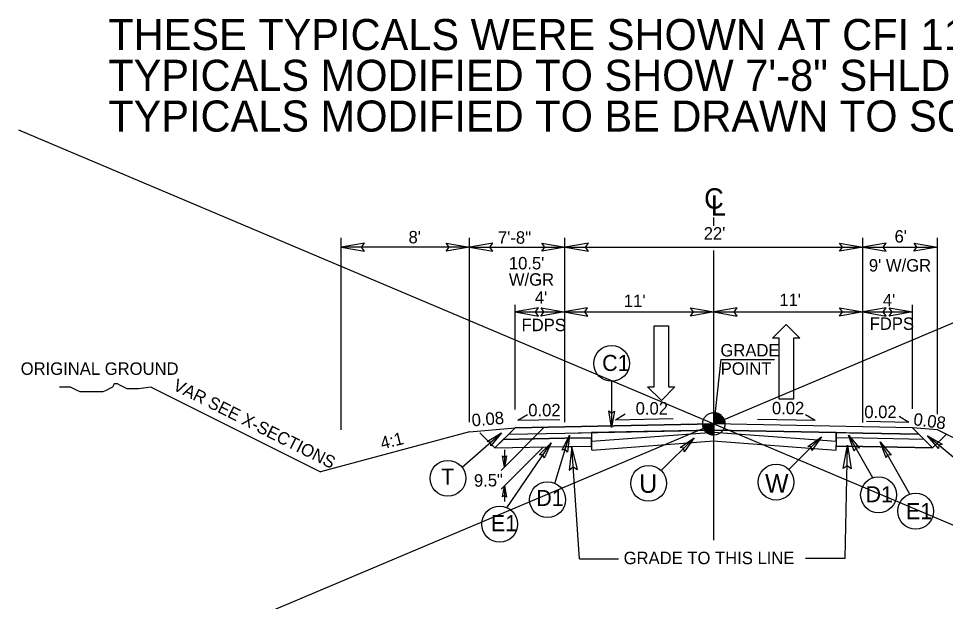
# Model space of a CAD drawing. Extents: x 573732 to 574187, y -53389 to -53257.
# Drawn here: x 574009.4 to 574084, y -53315.3 to -53268.4 of the extents above; entities that cross this region are included whole.
import ezdxf

# ---------------------------------------------------------------- set-up
doc = ezdxf.new("R2010")
doc.units = 0
for name, color, linetype in [('Default', 7, 'Continuous'), ('Old_Level_11', 7, 'Continuous'), ('Prop Dimension', 7, 'Continuous'), ('Prop Lane Arrow CELL', 7, 'Continuous'), ('Prop Shade Heavy', 7, 'Continuous'), ('Prop Shade Light', 7, 'Continuous'), ('Prop Shade Medium', 7, 'Continuous'), ('Typical Grade Point Symbol CELL', 7, 'Continuous'), ('Typical ID Circle CELL', 7, 'Continuous'), ('Typical Pavement Slope CELL', 7, 'Continuous'), ('Typical Pavement Slope Information CELL', 7, 'Continuous'), ('Typical Shoulder Slope CELL', 7, 'Continuous'), ('Typical Shoulder Slope Information CELL', 7, 'Continuous'), ('Typical Slope Point Local CELL', 7, 'Continuous'), ('Typical Terminator CELL', 7, 'Continuous'), ('Typical Text Centerline CELL', 7, 'Continuous'), ('Typical Text General CELL', 7, 'Continuous'), ('Typical Text Grade Point CELL', 7, 'Continuous'), ('Typical Text ID Circle CELL', 7, 'Continuous')]:
    doc.layers.add(name, color=color, linetype=linetype)

msp = doc.modelspace()

# ---------------------------------------------------------------- linework, layer by layer
at = {"layer": 'Default'}
for p, q in [((574009.442, -53277.39), (574121.356, -53324.666)), ((574121.356, -53277.39), (574009.442, -53324.666))]:
    msp.add_line(p, q, dxfattribs=at)
at = {"layer": 'Old_Level_11'}
for points in [[(574048.708, -53303.606), (574048.553, -53304.506), (574048.393, -53303.601), (574048.553, -53303.716)], [(574048.398, -53306.906), (574048.553, -53306.006), (574048.713, -53306.911), (574048.553, -53306.796)]]:
    msp.add_lwpolyline(points, close=True, dxfattribs=at)
at = {"layer": 'Prop Dimension'}
for p, q in [((574035.403, -53301.516), (574035.403, -53286.055)), ((574045.733, -53300.89), (574045.733, -53286.055)), ((574053.403, -53300.89), (574053.403, -53286.055)), ((574077.395, -53300.915), (574077.395, -53286.055)), ((574083.395, -53300.246), (574083.395, -53286.055)), ((574045.733, -53286.812), (574035.403, -53286.812)), ((574045.733, -53286.812), (574053.435, -53286.812)), ((574053.435, -53286.812), (574077.395, -53286.812)), ((574077.395, -53286.812), (574083.395, -53286.812)), ((574049.403, -53299.879), (574049.403, -53291.451)), ((574049.403, -53292.027), (574053.366, -53292.027)), ((574053.366, -53292.027), (574065.399, -53292.027)), ((574065.399, -53292.027), (574077.395, -53292.027)), ((574077.395, -53292.027), (574081.395, -53292.027)), ((574081.395, -53299.809), (574081.395, -53291.451)), ((574065.975, -53295.851), (574065.399, -53301.028)), ((574065.975, -53295.851), (574070.295, -53295.851)), ((574051.758, -53301.301), (574048.287, -53304.772)), ((574051.673, -53302.887), (574048.287, -53306.272)), ((574048.553, -53303.109), (574048.553, -53304.506)), ((574054.584, -53311.868), (574053.969, -53302.84)), ((574075.971, -53311.834), (574076.165, -53302.827)), ((574048.553, -53306.006), (574048.553, -53307.261)), ((574054.584, -53311.868), (574057.725, -53311.868)), ((574072.786, -53311.834), (574075.971, -53311.834))]:
    msp.add_line(p, q, dxfattribs=at)
at = {"layer": 'Prop Lane Arrow CELL'}
for p, q in [((574060.593, -53298.034), (574060.593, -53293.134)), ((574060.593, -53293.134), (574061.748, -53293.134)), ((574061.748, -53293.134), (574061.748, -53298.034)), ((574070.127, -53294.14), (574071.212, -53293.037)), ((574071.212, -53293.037), (574072.332, -53294.14)), ((574070.652, -53294.14), (574070.127, -53294.14)), ((574070.652, -53299.04), (574070.652, -53294.14)), ((574072.332, -53294.14), (574071.807, -53294.14)), ((574071.807, -53294.14), (574071.807, -53299.04)), ((574061.188, -53299.137), (574060.068, -53298.034)), ((574060.068, -53298.034), (574060.593, -53298.034)), ((574062.273, -53298.034), (574061.188, -53299.137)), ((574061.748, -53298.034), (574062.273, -53298.034)), ((574071.807, -53299.04), (574070.652, -53299.04))]:
    msp.add_line(p, q, dxfattribs=at)
at = {"layer": 'Prop Shade Heavy'}
for points in [[(574065.399, -53301.528), (574065.389, -53301.528), (574055.56, -53301.725), (574055.56, -53302.141), (574055.56, -53302.424), (574065.399, -53301.681), (574065.399, -53301.528)], [(574065.409, -53301.528), (574065.399, -53301.528), (574065.399, -53301.681), (574075.238, -53302.424), (574075.238, -53302.141), (574075.238, -53301.725), (574065.409, -53301.528)]]:
    msp.add_lwpolyline(points, dxfattribs=at)
at = {"layer": 'Prop Shade Light'}
for p, q in [((574065.399, -53301.028), (574053.403, -53301.268)), ((574077.395, -53301.268), (574065.399, -53301.028)), ((574049.403, -53301.35), (574048.893, -53301.86)), ((574048.893, -53301.86), (574053.413, -53301.767)), ((574053.403, -53301.268), (574049.403, -53301.35)), ((574053.413, -53301.767), (574055.56, -53301.725)), ((574055.56, -53301.725), (574065.389, -53301.528)), ((574065.389, -53301.528), (574065.399, -53301.528)), ((574075.238, -53301.725), (574077.385, -53301.767)), ((574077.385, -53301.767), (574081.905, -53301.86)), ((574081.395, -53301.35), (574077.395, -53301.268)), ((574081.905, -53301.86), (574081.395, -53301.35))]:
    msp.add_line(p, q, dxfattribs=at)
msp.add_lwpolyline([(574065.399, -53301.528), (574065.409, -53301.528), (574075.238, -53301.725)], dxfattribs=at)
at = {"layer": 'Prop Shade Medium'}
for p, q in [((574048.467, -53302.286), (574047.787, -53302.966)), ((574053.422, -53302.184), (574048.467, -53302.286)), ((574055.56, -53302.141), (574053.422, -53302.184)), ((574055.56, -53302.424), (574055.56, -53302.141)), ((574055.56, -53302.725), (574055.56, -53302.424)), ((574077.376, -53302.184), (574075.238, -53302.141)), ((574082.331, -53302.286), (574077.376, -53302.184)), ((574083.012, -53302.966), (574082.331, -53302.286)), ((574047.787, -53302.966), (574053.436, -53302.851)), ((574055.56, -53302.808), (574055.56, -53302.725)), ((574075.238, -53302.725), (574075.238, -53302.808)), ((574075.238, -53302.808), (574076.15, -53302.826)), ((574076.179, -53302.827), (574077.363, -53302.851)), ((574077.363, -53302.851), (574083.012, -53302.966))]:
    msp.add_line(p, q, dxfattribs=at)
for points in [[(574075.238, -53302.141), (574075.238, -53302.424), (574075.238, -53302.725)], [(574053.436, -53302.851), (574053.969, -53302.84), (574055.56, -53302.808)], [(574076.15, -53302.826), (574076.166, -53302.743), (574076.179, -53302.827)]]:
    msp.add_lwpolyline(points, dxfattribs=at)
at = {"layer": 'Typical Grade Point Symbol CELL'}
for p, q in [((574065.399, -53301.028), (574065.399, -53300.132)), ((574064.504, -53301.028), (574065.399, -53301.028)), ((574065.397, -53301.923), (574065.399, -53301.028)), ((574065.399, -53301.028), (574065.397, -53301.923)), ((574066.294, -53301.028), (574065.399, -53301.028))]:
    msp.add_line(p, q, dxfattribs=at)
for points in [[(574065.407, -53300.132), (574065.407, -53300.132), (574065.407, -53301.028)], [(574065.425, -53300.132), (574065.425, -53301.028)], [(574065.443, -53300.134), (574065.443, -53301.028)], [(574065.461, -53300.134), (574065.461, -53301.028)], [(574065.479, -53300.136), (574065.479, -53301.028)], [(574065.497, -53300.138), (574065.497, -53301.028)], [(574065.514, -53300.14), (574065.514, -53301.028)], [(574065.532, -53300.142), (574065.532, -53301.028)], [(574065.55, -53300.144), (574065.55, -53301.028)], [(574065.568, -53300.148), (574065.568, -53301.028)], [(574065.586, -53300.152), (574065.586, -53301.028)], [(574065.604, -53300.156), (574065.604, -53301.028)], [(574065.622, -53300.16), (574065.622, -53301.028)], [(574065.64, -53300.166), (574065.64, -53301.028)], [(574065.658, -53300.17), (574065.658, -53301.028)], [(574065.676, -53300.176), (574065.676, -53301.028)], [(574065.694, -53300.182), (574065.694, -53301.028)], [(574065.711, -53300.188), (574065.711, -53301.028)], [(574065.729, -53300.196), (574065.729, -53301.028)], [(574065.747, -53300.204), (574065.747, -53301.028)], [(574065.765, -53300.212), (574065.765, -53301.028)], [(574065.783, -53300.22), (574065.783, -53301.028)], [(574065.801, -53300.228), (574065.801, -53301.028)], [(574065.819, -53300.238), (574065.819, -53301.028)], [(574065.837, -53300.248), (574065.837, -53301.028)], [(574065.855, -53300.258), (574065.855, -53301.028)], [(574065.873, -53300.268), (574065.873, -53301.028)], [(574065.89, -53300.28), (574065.89, -53301.028)], [(574065.908, -53300.292), (574065.908, -53301.028)], [(574065.926, -53300.305), (574065.926, -53301.028)], [(574065.944, -53300.317), (574065.944, -53301.028)], [(574064.508, -53301.028), (574064.508, -53301.125)], [(574064.526, -53301.028), (574064.526, -53301.231)], [(574064.544, -53301.028), (574064.544, -53301.294)], [(574064.562, -53301.028), (574064.562, -53301.348)], [(574064.58, -53301.028), (574064.58, -53301.39)], [(574064.597, -53301.028), (574064.597, -53301.427)], [(574064.615, -53301.028), (574064.615, -53301.461)], [(574064.633, -53301.028), (574064.633, -53301.493)], [(574064.651, -53301.028), (574064.651, -53301.521)], [(574064.669, -53301.028), (574064.669, -53301.547)], [(574064.687, -53301.028), (574064.687, -53301.571)], [(574064.705, -53301.028), (574064.705, -53301.593)], [(574064.723, -53301.028), (574064.723, -53301.614)], [(574064.741, -53301.028), (574064.741, -53301.634)], [(574064.759, -53301.028), (574064.759, -53301.654)], [(574064.776, -53301.028), (574064.776, -53301.672)], [(574064.794, -53301.028), (574064.794, -53301.688)], [(574064.812, -53301.028), (574064.812, -53301.704)], [(574064.83, -53301.028), (574064.83, -53301.72)], [(574064.848, -53301.028), (574064.848, -53301.734)], [(574064.866, -53301.028), (574064.866, -53301.748)], [(574064.884, -53301.028), (574064.884, -53301.76)], [(574064.902, -53301.028), (574064.902, -53301.772)], [(574064.92, -53301.028), (574064.92, -53301.784)], [(574064.938, -53301.028), (574064.938, -53301.795)], [(574064.956, -53301.028), (574064.956, -53301.805)], [(574064.973, -53301.028), (574064.973, -53301.815)], [(574064.991, -53301.028), (574064.991, -53301.825)], [(574065.009, -53301.028), (574065.009, -53301.833)], [(574065.027, -53301.028), (574065.027, -53301.841)], [(574065.045, -53301.028), (574065.045, -53301.849)], [(574065.063, -53301.028), (574065.063, -53301.857)], [(574065.081, -53301.028), (574065.081, -53301.865)], [(574065.099, -53301.028), (574065.099, -53301.871)], [(574065.117, -53301.028), (574065.117, -53301.877)], [(574065.135, -53301.028), (574065.135, -53301.883)], [(574065.152, -53301.028), (574065.152, -53301.887)], [(574065.17, -53301.028), (574065.17, -53301.893)], [(574065.188, -53301.028), (574065.188, -53301.897)], [(574065.206, -53301.028), (574065.206, -53301.901)], [(574065.224, -53301.028), (574065.224, -53301.905)], [(574065.242, -53301.028), (574065.242, -53301.909)], [(574065.26, -53301.028), (574065.26, -53301.911)], [(574065.278, -53301.028), (574065.278, -53301.915)], [(574065.296, -53301.028), (574065.296, -53301.917)], [(574065.314, -53301.028), (574065.314, -53301.919)], [(574065.331, -53301.028), (574065.331, -53301.921)], [(574065.349, -53301.028), (574065.349, -53301.921)], [(574065.367, -53301.028), (574065.367, -53301.923)], [(574065.385, -53301.028), (574065.385, -53301.923), (574065.385, -53301.923)], [(574065.962, -53300.331), (574065.962, -53301.028)], [(574065.98, -53300.347), (574065.98, -53301.028)], [(574065.998, -53300.363), (574065.998, -53301.028)], [(574066.016, -53300.379), (574066.016, -53301.028)], [(574066.034, -53300.397), (574066.034, -53301.028)], [(574066.052, -53300.415), (574066.052, -53301.028)], [(574066.069, -53300.435), (574066.069, -53301.028)], [(574066.087, -53300.457), (574066.087, -53301.028)], [(574066.105, -53300.479), (574066.105, -53301.028)], [(574066.123, -53300.502), (574066.123, -53301.028)], [(574066.141, -53300.528), (574066.141, -53301.028)], [(574066.159, -53300.556), (574066.159, -53301.028)], [(574066.177, -53300.586), (574066.177, -53301.028)], [(574066.195, -53300.618), (574066.195, -53301.028)], [(574066.213, -53300.656), (574066.213, -53301.028)], [(574066.231, -53300.697), (574066.231, -53301.028)], [(574066.249, -53300.747), (574066.249, -53301.028)], [(574066.266, -53300.809), (574066.266, -53301.028)], [(574066.284, -53300.9), (574066.284, -53301.028)]]:
    msp.add_lwpolyline(points, dxfattribs=at)
msp.add_circle((574065.398, -53301.027), 0.895, dxfattribs=at)
for start, end in [(359.99048, 89.99048), (179.99048, 269.99048)]:
    msp.add_arc((574065.398, -53301.027), 0.895, start, end, dxfattribs=at)
at = {"layer": 'Typical ID Circle CELL'}
for p, q in [((574057.175, -53297.602), (574057.175, -53301.33)), ((574045.135, -53304.513), (574048.304, -53301.735)), ((574048.737, -53307.766), (574052.298, -53302.549)), ((574052.611, -53305.808), (574053.79, -53301.935)), ((574061.17, -53304.789), (574063.807, -53302.153)), ((574071.426, -53304.691), (574074.063, -53302.055)), ((574078.194, -53305.369), (574076.249, -53301.939)), ((574081.179, -53306.681), (574078.798, -53302.483)), ((574085.439, -53304.353), (574082.598, -53301.987))]:
    msp.add_line(p, q, dxfattribs=at)
for centre in [(574057.175, -53296.16), (574044.001, -53305.404), (574060.151, -53305.809), (574070.407, -53305.711), (574078.659, -53306.735), (574052.018, -53307.123), (574081.643, -53308.047), (574048.165, -53309.091)]:
    msp.add_circle(centre, 1.443, dxfattribs=at)
at = {"layer": 'Typical Pavement Slope CELL'}
for p, q in [((574053.403, -53301.268), (574065.399, -53301.028)), ((574077.395, -53301.268), (574065.399, -53301.028)), ((574053.413, -53301.767), (574065.409, -53301.528)), ((574077.385, -53301.767), (574065.389, -53301.528)), ((574053.422, -53302.184), (574055.56, -53302.141)), ((574077.376, -53302.184), (574075.238, -53302.141)), ((574053.435, -53302.851), (574055.574, -53302.808)), ((574077.363, -53302.851), (574075.224, -53302.808))]:
    msp.add_line(p, q, dxfattribs=at)
at = {"layer": 'Typical Pavement Slope Information CELL'}
for p, q in [((574049.619, -53300.735), (574050.402, -53300.262)), ((574057.478, -53300.688), (574058.261, -53300.215)), ((574073.564, -53300.763), (574072.781, -53300.29)), ((574049.619, -53300.735), (574053.014, -53300.668)), ((574057.478, -53300.688), (574062.138, -53300.595)), ((574073.564, -53300.763), (574068.904, -53300.67)), ((574081.094, -53300.907), (574077.699, -53300.839)), ((574081.094, -53300.907), (574080.311, -53300.434))]:
    msp.add_line(p, q, dxfattribs=at)
at = {"layer": 'Typical Shoulder Slope CELL'}
for p, q in [((574045.738, -53301.655), (574049.403, -53301.35)), ((574047.787, -53302.966), (574046.562, -53301.742)), ((574047.787, -53302.966), (574049.403, -53301.35)), ((574048.893, -53301.86), (574053.414, -53301.767)), ((574049.403, -53301.35), (574053.403, -53301.268)), ((574055.56, -53302.424), (574065.399, -53301.681)), ((574055.56, -53301.725), (574055.56, -53302.725)), ((574065.399, -53301.681), (574075.238, -53302.424)), ((574075.238, -53301.725), (574075.238, -53302.725)), ((574081.905, -53301.86), (574077.385, -53301.767)), ((574081.395, -53301.35), (574077.395, -53301.268)), ((574083.395, -53301.516), (574081.395, -53301.35)), ((574083.012, -53302.966), (574081.395, -53301.35)), ((574048.467, -53302.286), (574053.422, -53302.184)), ((574055.614, -53303.132), (574065.399, -53302.393)), ((574065.346, -53302.389), (574075.238, -53303.136)), ((574082.331, -53302.286), (574077.376, -53302.184)), ((574083.012, -53302.966), (574084.106, -53301.872)), ((574047.787, -53302.966), (574053.436, -53302.851)), ((574055.56, -53302.724), (574055.56, -53303.136)), ((574075.238, -53303.136), (574075.238, -53302.725)), ((574083.012, -53302.966), (574077.362, -53302.851))]:
    msp.add_line(p, q, dxfattribs=at)
at = {"layer": 'Typical Slope Point Local CELL'}
for p, q in [((574020.121, -53298.074), (574033.738, -53304.882)), ((574045.738, -53301.655), (574033.738, -53304.882)), ((574105.895, -53312.767), (574083.395, -53301.516))]:
    msp.add_line(p, q, dxfattribs=at)
msp.add_lwpolyline([(574020.121, -53298.074), (574019.084, -53298.203), (574018.825, -53298.203), (574018.435, -53298.203), (574018.176, -53298.203), (574017.916, -53298.074), (574017.657, -53297.944), (574017.398, -53297.814), (574017.138, -53297.814), (574017.008, -53298.074), (574016.749, -53298.203), (574016.49, -53298.333), (574016.23, -53298.462), (574015.971, -53298.462), (574015.712, -53298.462), (574015.452, -53298.462), (574015.193, -53298.462), (574014.934, -53298.462), (574014.674, -53298.462), (574014.415, -53298.462), (574014.156, -53298.333), (574013.896, -53298.203), (574013.637, -53298.074), (574013.247, -53298.074), (574012.988, -53298.074), (574012.729, -53298.074)], dxfattribs=at)
at = {"layer": 'Typical Terminator CELL'}
for points in [[(574037.278, -53286.489), (574035.403, -53286.812), (574037.289, -53287.145), (574037.049, -53286.812)], [(574043.859, -53286.489), (574045.733, -53286.812), (574043.848, -53287.145), (574044.088, -53286.812)], [(574047.608, -53286.489), (574045.733, -53286.812), (574047.619, -53287.145), (574047.379, -53286.812)], [(574051.56, -53286.489), (574053.435, -53286.812), (574051.55, -53287.145), (574051.789, -53286.812)], [(574055.31, -53286.489), (574053.435, -53286.812), (574055.32, -53287.145), (574055.08, -53286.812)], [(574075.52, -53286.489), (574077.395, -53286.812), (574075.51, -53287.145), (574075.749, -53286.812)], [(574079.269, -53286.489), (574077.395, -53286.812), (574079.28, -53287.145), (574079.04, -53286.812)], [(574081.52, -53286.489), (574083.395, -53286.812), (574081.51, -53287.145), (574081.749, -53286.812)], [(574051.278, -53291.705), (574049.403, -53292.027), (574051.289, -53292.361), (574051.049, -53292.027)], [(574051.491, -53291.705), (574053.366, -53292.027), (574051.481, -53292.361), (574051.721, -53292.027)], [(574055.241, -53291.705), (574053.366, -53292.027), (574055.251, -53292.361), (574055.012, -53292.027)], [(574063.524, -53291.705), (574065.399, -53292.027), (574063.514, -53292.361), (574063.754, -53292.027)], [(574067.274, -53291.705), (574065.399, -53292.027), (574067.284, -53292.361), (574067.045, -53292.027)], [(574075.52, -53291.705), (574077.395, -53292.027), (574075.51, -53292.361), (574075.749, -53292.027)], [(574079.269, -53291.705), (574077.395, -53292.027), (574079.28, -53292.361), (574079.04, -53292.027)], [(574079.52, -53291.705), (574081.395, -53292.027), (574079.51, -53292.361), (574079.749, -53292.027)], [(574057.405, -53299.995), (574057.175, -53301.33), (574056.937, -53299.987), (574057.175, -53300.158)], [(574047.148, -53302.442), (574048.304, -53301.735), (574047.45, -53302.799), (574047.422, -53302.508)], [(574051.355, -53303.522), (574052.298, -53302.549), (574051.737, -53303.792), (574051.637, -53303.517)], [(574053.181, -53303.146), (574053.79, -53301.935), (574053.626, -53303.289), (574053.448, -53303.057)], [(574062.7, -53302.935), (574063.807, -53302.153), (574063.025, -53303.27), (574062.978, -53302.982)], [(574072.956, -53302.836), (574074.063, -53302.055), (574073.281, -53303.172), (574073.234, -53302.884)], [(574076.708, -53303.214), (574076.249, -53301.939), (574077.118, -53302.99), (574076.827, -53302.959)], [(574079.257, -53303.759), (574078.798, -53302.483), (574079.667, -53303.534), (574079.376, -53303.503)], [(574083.477, -53303.019), (574082.598, -53301.987), (574083.782, -53302.664), (574083.499, -53302.738)], [(574054.419, -53304.688), (574053.969, -53302.84), (574053.765, -53304.743), (574054.081, -53304.482)], [(574075.803, -53304.611), (574076.166, -53302.743), (574076.459, -53304.635), (574076.131, -53304.389)]]:
    msp.add_lwpolyline(points, close=True, dxfattribs=at)
at = {"layer": 'Typical Text Centerline CELL'}
for p, q in [((574065.399, -53285.095), (574065.399, -53284.438)), ((574065.399, -53310.372), (574065.399, -53287.093))]:
    msp.add_line(p, q, dxfattribs=at)

# ---------------------------------------------------------------- texts
at = {"layer": 'Default'}
for s, p in [('THESE TYPICALS WERE SHOWN AT CFI 11-21-13.', (574016.662, -53270.966)), ('TYPICALS MODIFIED TO SHOW 7\'-8" SHLDRS ON LT SIDE.', (574016.662, -53274.243)), ('TYPICALS MODIFIED TO BE DRAWN TO SCALE.', (574016.662, -53277.52))]:
    msp.add_text(s, height=2.5, dxfattribs=at).set_placement(p)
at = {"layer": 'Typical Pavement Slope Information CELL'}
for s, p in [("22'", (574064.588, -53286.203)), ("8'", (574040.828, -53286.508)), ('7\'-8"', (574048.028, -53286.536)), ("6'", (574079.946, -53286.447)), ("10.5'", (574048.904, -53288.603)), ("9' W/GR", (574077.878, -53288.773)), ('W/GR', (574048.904, -53289.914)), ("4'", (574050.996, -53291.362)), ("11'", (574070.673, -53291.559)), ("4'", (574079.009, -53291.568)), ("11'", (574058.158, -53291.628)), ('FDPS', (574049.926, -53293.571)), ('FDPS', (574077.944, -53293.466)), ('ORIGINAL GROUND', (574009.615, -53297.082)), ('0.02', (574059.109, -53300.275)), ('0.02', (574070.077, -53300.254))]:
    msp.add_text(s, height=1, rotation=360, dxfattribs=at).set_placement(p)
at = {"layer": 'Typical Shoulder Slope Information CELL'}
for s, rotation, p in [('0.02', 360, (574050.466, -53300.421)), ('0.02', 360, (574077.512, -53300.56)), ('0.08', 4.76147, (574045.954, -53301.235)), ('0.08', 352.40536, (574081.418, -53301.124)), ('9.5"', 1.14574, (574046.104, -53306.086))]:
    msp.add_text(s, height=1, rotation=rotation, dxfattribs=at).set_placement(p)
at = {"layer": 'Typical Slope Point Local CELL'}
for s, rotation, p in [('VAR SEE X-SECTIONS', 333.43495, (574021.793, -53298.25)), ('4:1', 14.03624, (574038.703, -53303.083))]:
    msp.add_text(s, height=1, rotation=rotation, dxfattribs=at).set_placement(p)
at = {"layer": 'Typical Text Centerline CELL'}
msp.add_text('C', height=1.64, dxfattribs=at).set_placement((574064.619, -53283.72))
msp.add_text('L', height=1.641, rotation=359.9469, dxfattribs=at).set_placement((574065.164, -53284.28))
at = {"layer": 'Typical Text General CELL'}
msp.add_text('GRADE TO THIS LINE', height=1, dxfattribs=at).set_placement((574058.142, -53312.308))
at = {"layer": 'Typical Text Grade Point CELL'}
for s, p in [('GRADE', (574065.932, -53295.604)), ('POINT', (574065.953, -53297.076))]:
    msp.add_text(s, height=1, dxfattribs=at).set_placement(p)
at = {"layer": 'Typical Text ID Circle CELL'}
for s, height, p in [('C1', 1.2912, (574056.411, -53296.77)), ('T ', 1.2912, (574043.458, -53305.924)), ('U', 1.5, (574059.396, -53306.574)), ('W', 1.5, (574069.524, -53306.562)), ('D1', 1.2912, (574077.613, -53307.329)), ('D1', 1.2912, (574051.111, -53307.63)), ('E1', 1.2912, (574080.863, -53308.691)), ('E1', 1.2912, (574047.455, -53309.659))]:
    msp.add_text(s, height=height, dxfattribs=at).set_placement(p)

doc.saveas('drawing.dxf')
